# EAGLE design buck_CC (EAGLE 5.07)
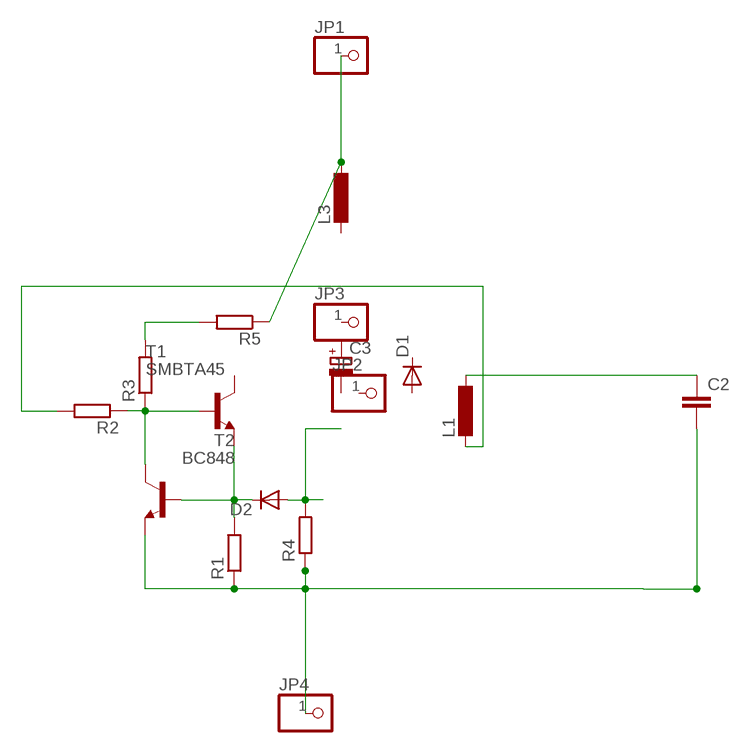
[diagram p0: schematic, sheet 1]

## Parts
C2  C-EUC0805  [C0805]
C3  CPOL-EUE2.5-6  [E2,5-6]
D1  DIODE-SMA-DO214  [SMA-DO214AC]
D2  DIODE-MINIMELF  [MINIMELF]
JP1  PINHD-1X11MM6  [1X1MM8]
JP2  PINHD-1X11MM6  [1X1MM8]
JP3  PINHD-1X11MM6  [1X1MM8]
JP4  PINHD-1X11MM6  [1X1MM8]
L1  L-EU0207/10  [0207/10]
L3  L-EU0204V  [0204V]
R1  R-EU_R0805  [R0805]
R2  R-EU_R0805  [R0805]
R3  R-EU_R1206  [R1206]
R4  R-EU_R0805  [R0805]
R5  R-EU_R1206  [R1206]
T1  SMBTA45  BC848  [SOT23]
T2  BC848  [SOT23]

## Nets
B1C2: R2.1 R3.1 T1.B T2.C
EB: D2.C R1.2 T1.E T2.B
N$1: R3.2 R5.2
N$4: L1.2 R2.2
N$6: C2.1 L1.1
NDOT: D2.A R4.2
V+: JP1.1 L3.1 R5.1
V-: C2.2 JP4.1 R1.1 R4.1 T2.E
Unconnected: C3.+ C3.- D1.A D1.K(C) JP2.1 JP3.1 L3.2 T1.C

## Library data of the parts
C2 = rcl:C-EU: CAPACITOR, European symbol
C3 = rcl:CPOL-EU: POLARIZED CAPACITOR, European symbol
D1 D2 = diode:DIODE-: DIODE
JP1-JP4 = pinhead:PINHD-1X1: PIN HEADER
L1 L3 = rcl:L-EU: INDUCTOR, European symbol
R1-R5 = rcl:R-EU_: RESISTOR, European symbol
T1 T2 = transistor:BC848: NPN TRANSISTOR

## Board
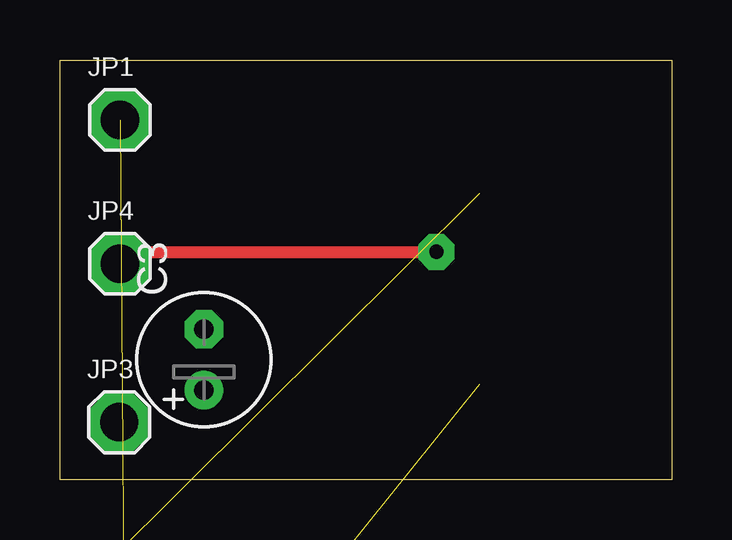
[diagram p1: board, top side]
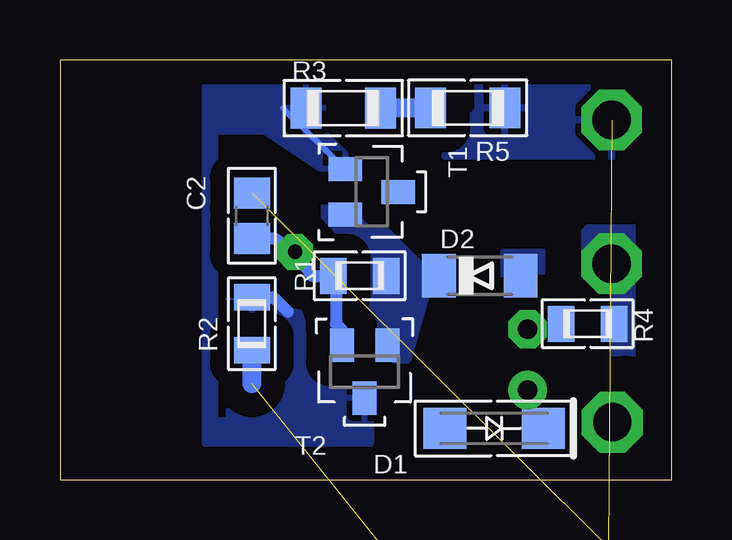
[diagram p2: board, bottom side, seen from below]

Size 25.5 x 17.5 mm. Coordinates in mm from the lower left corner, seen from the top.
Outline: 0,17.5 25.5,17.5 25.5,0 0,0 0,17.5
Copper layers (1*16): Top 0.035mm / dielectric 1.5mm / Bottom 0.035mm
Design rules "default *": minimum track width 10mil, minimum drill 20mil, track to track 8mil, track to pad 8mil, pad to pad 8mil, via to via 8mil, smd to smd 8mil, copper to edge 40mil, drill to drill 8mil, minimum pad ring 1mil, minimum via ring 8mil, stop-mask expansion 4mil, vias tented up to drill 0mil, thermal gap 10mil

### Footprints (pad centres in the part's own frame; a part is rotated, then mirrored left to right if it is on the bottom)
C0805 = smd 1.3 x 1.5: 1 -0.95,0; 2 0.95,0
E2,5-6 = drill 0.8 pad 1.6 round: + -1.27,0 | drill 0.8 pad 1.6 octagon: - 1.27,0
SMA-DO214AC = smd 1.8 x 1.7: A 2.05,-0.127; K -2.05,-0.127
MINIMELF = smd 1.4 x 1.8: A 1.7,0; C -1.7,0
1X1MM8 = drill 1.6 pad 2.54 octagon: 1 0,0
0207/10 = drill 0.813 octagon: 1 -5.08,0; 2 5.08,0
0204V = drill 0.813 octagon: 1 -1.27,0; 2 1.27,0
R0805 = smd 1.1 x 1.5: 1 -1.1,0; 2 1.1,0
R1206 = smd 1.3 x 1.7: 1 -1.55,0; 2 1.55,0
SOT23 = smd 1 x 1.4: B -0.95,-1.1; C 0,1.1; E 0.95,-1.1

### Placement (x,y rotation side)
C2  17.5,11 270 bottom
C3  6,5 90 top
D1  7.39,2.01 180 bottom
D2  8,8.5 0 bottom
JP1  2.5,15 0 top
JP2  not placed on the board
JP3  2.47,2.39 0 top
JP4  2.5,9 0 top
L1  not placed on the board
L3  not placed on the board
R1  13,8.5 0 bottom
R2  17.5,6.5 270 bottom
R3  13.69,15.49 0 bottom
R4  3.5,6.5 180 bottom
R5  8.5,15.5 180 bottom
T1  12.5,12 270 bottom
T2  12.8,4.5 180 bottom

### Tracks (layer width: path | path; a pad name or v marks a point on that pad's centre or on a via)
B1C2
  Bottom 0.254: T1.B 16.19,15.5
  Bottom 0.5: R2.1 16.6,7.6 16,7
  pour Bottom (isolate 1, rank 3): 14.5,16.5 19.5,16.5 19.5,1.5 12.5,1.5 12.5,4.5 14,4.5 15,5.5 15.5,7 18.5,7.5 18.5,2.5 19,2.5 19,14.5 17,14.5 14,12.5 13,13 14.5,14.5
EB
  pour Bottom (isolate 1, no thermals): 11,5 10,8.5 13,11.5 14.5,11.5 14.5,10.5 13,10 12.5,9.5 12.5,5.5 12,5
N$1
  Bottom 0.8: R5.2 R3.2
N$4  (1 unrouted)
  Bottom 0.8: 17.5,4 R2.2
N$6  (1 unrouted)
NDOT
  pour Bottom (isolate 1.5, rank 3, no thermals): 4,7 4,6 4.5,5.5 9,5.5 9.5,6 9.5,6.5 9,7 7,7 7,9.5 5,9.5 5,8
V+  (1 unrouted)
  pour Bottom (isolate 1, rank 4): 3,16.5 6,16.5 8.1,16.4 8.1,15.4 9,14.5 9.5,13.5 2,13.5
V-  (via drill 0.6 pad 1.5)
  Top 0.5: v15.7,9.5 3,9.5 JP4.1
  Bottom 0.254: C2.2 17.93,10
  Bottom 0.5: C2.2 16.55,10.05 v15.7,9.5 15,8.5 R1.1 14,8.4 14,6.5 13.75,6.25 T2.E
  pour Bottom (isolate 1.5, rank 4, no thermals): 1,10.5 3.5,10.5 4,10 4,8.5 3,7.5 3,5 1,5 1,9.5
